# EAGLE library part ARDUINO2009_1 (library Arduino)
The Arduino Duemilanove ("2009") is a microcontroller board based on the ATmega168 or ATmega328. - 14 digital input/output pins (of which 6 can be used as PWM outputs) - 6 analog inputs, a 16 MHz crystal oscillator - USB connection - power jack - ISP header - reset button It contains everything needed to support the microcontroller; simply connect it to a computer with a USB cable or power it with a AC-to-DC adapter or battery to get started http://arduino.cc/en/Main/ArduinoBoardDuemilanove
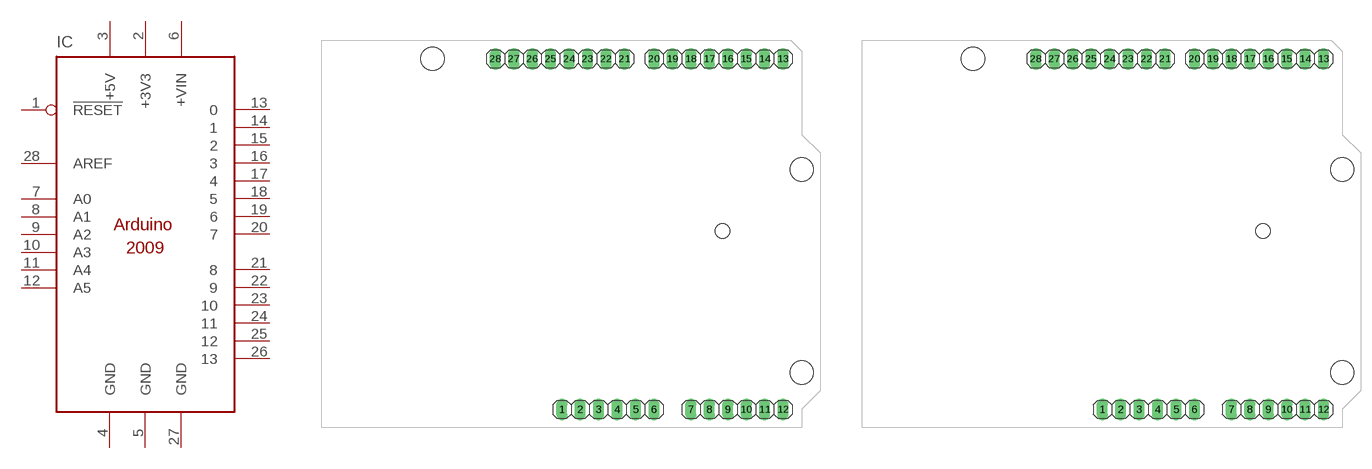
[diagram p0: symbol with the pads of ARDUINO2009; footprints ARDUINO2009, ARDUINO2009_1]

Designator prefix IC

## ARDUINO2009_10  [ARDUINO2009]
1  !RESET
2  +3V3  pwr
3  +5V  pwr
4  GND  pwr
5  GND  pwr
6  +VIN
7  A0
8  A1
9  A2
10  A3
11  A4
12  A5
13  0
14  1
15  2
16  3
17  4
18  5
19  6
20  7
21  8
22  9
23  10
24  11
25  12
26  13
27  GND  pwr
28  AREF

## ARDUINO2009_11  [ARDUINO2009_1]
Pads as for ARDUINO2009

## ARDUINO2009_12  [ARDUINO2009_2]
Pads as for ARDUINO2009

## Footprint ARDUINO2009 (pad centres in mm)
drill 1.016 long: 1 33.02,2.54; 2 35.56,2.54; 3 38.1,2.54; 4 40.64,2.54; 5 43.18,2.54; 6 45.72,2.54; 7 50.8,2.54; 8 53.34,2.54; 9 55.88,2.54; 10 58.42,2.54; 11 60.96,2.54; 12 63.5,2.54; 13 63.5,50.8; 14 60.96,50.8; 15 58.42,50.8; 16 55.88,50.8; 17 53.34,50.8; 18 50.8,50.8; 19 48.26,50.8; 20 45.72,50.8; 21 41.656,50.8; 22 39.116,50.8; 23 36.576,50.8; 24 34.036,50.8; 25 31.496,50.8; 26 28.956,50.8; 27 26.416,50.8; 28 23.876,50.8
hole 3.2 at 15.24,50.8
hole 3.2 at 66.04,35.56
hole 3.2 at 66.04,7.62
hole 2 at 55.17,27.114

## Footprint ARDUINO2009_1 (pad centres in mm)
drill 1.016 long: 1 33.02,2.54; 2 35.56,2.54; 3 38.1,2.54; 4 40.64,2.54; 5 43.18,2.54; 6 45.72,2.54; 7 50.8,2.54; 8 53.34,2.54; 9 55.88,2.54; 10 58.42,2.54; 11 60.96,2.54; 12 63.5,2.54; 13 63.5,50.8; 14 60.96,50.8; 15 58.42,50.8; 16 55.88,50.8; 17 53.34,50.8; 18 50.8,50.8; 19 48.26,50.8; 20 45.72,50.8; 21 41.656,50.8; 22 39.116,50.8; 23 36.576,50.8; 24 34.036,50.8; 25 31.496,50.8; 26 28.956,50.8; 27 26.416,50.8; 28 23.876,50.8
hole 3.2 at 15.24,50.8
hole 3.2 at 66.04,35.56
hole 3.2 at 66.04,7.62
hole 2 at 55.17,27.114

## Footprint ARDUINO2009_2 (pad centres in mm)
drill 1.016 long: 1 33.02,2.54; 2 35.56,2.54; 3 38.1,2.54; 4 40.64,2.54; 5 43.18,2.54; 6 45.72,2.54; 7 50.8,2.54; 8 53.34,2.54; 9 55.88,2.54; 10 58.42,2.54; 11 60.96,2.54; 12 63.5,2.54; 13 63.5,50.8; 14 60.96,50.8; 15 58.42,50.8; 16 55.88,50.8; 17 53.34,50.8; 18 50.8,50.8; 19 48.26,50.8; 20 45.72,50.8; 21 41.656,50.8; 22 39.116,50.8; 23 36.576,50.8; 24 34.036,50.8; 25 31.496,50.8; 26 28.956,50.8; 27 26.416,50.8; 28 23.876,50.8
hole 3.2 at 15.24,50.8
hole 3.2 at 66.04,35.56
hole 3.2 at 66.04,7.62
